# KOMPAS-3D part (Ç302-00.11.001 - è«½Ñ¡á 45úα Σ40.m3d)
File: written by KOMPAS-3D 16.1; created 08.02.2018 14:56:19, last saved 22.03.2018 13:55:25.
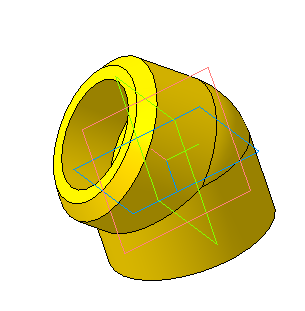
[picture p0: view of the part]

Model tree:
1. Фаска:1
     Угол = 45; Длина 1 = 5; Длина 2 = 5

Referenced files in Z:\1 ПКИ 3D\Полипропиленовые фитинги, трубы\: Колено 45гр 40 FV PPR ф. FV PLAST.m3d
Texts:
  (ф) Колено 45гр 40 FV PPR ф. FV PLAST
  Колено 45гр ф40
